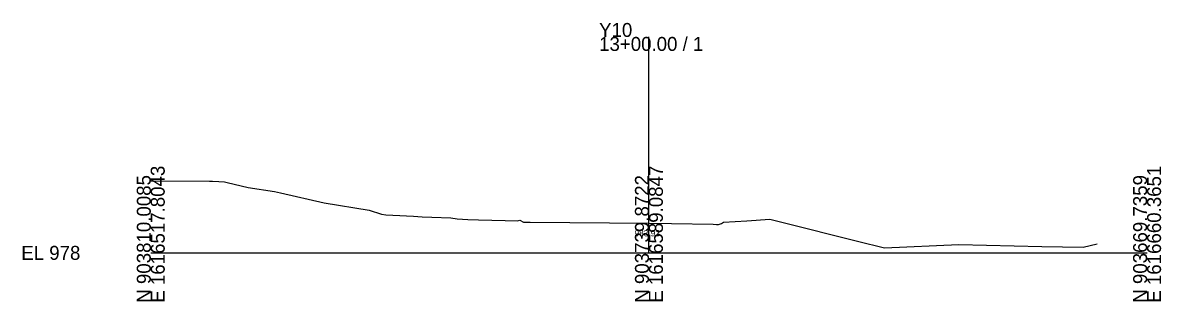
# Model space of a CAD drawing. Extents: x -26 to 203, y -10 to 3046.
# Drawn here: x -25.7 to 202.8, y 2990.3 to 3046.1 of the extents above; entities that cross this region are included whole.
import ezdxf

# ---------------------------------------------------------------- set-up
doc = ezdxf.new("R2010")
doc.units = 0
for name, color, linetype in [('Exist Cross Section Cell', 7, 'Continuous'), ('Exist XS Center Line Elevation Label', 7, 'Continuous'), ('Exist XS Ground Line', 7, 'Continuous')]:
    doc.layers.add(name, color=color, linetype=linetype)

msp = doc.modelspace()

# ---------------------------------------------------------------- linework, layer by layer
at = {"layer": 'Exist Cross Section Cell'}
for p, q in [((100, 3000), (100, 3043.3)), ((0, 3000), (100, 3000)), ((100, 3000), (200, 3000))]:
    msp.add_line(p, q, dxfattribs=at)
at = {"layer": 'Exist XS Ground Line'}
for p, q in [((0, 3014.43), (11.76, 3014.41)), ((11.76, 3014.41), (12.39, 3014.4)), ((12.39, 3014.4), (13.68, 3014.31)), ((13.68, 3014.31), (14.81, 3014.22)), ((14.81, 3014.22), (15.33, 3014.1)), ((15.33, 3014.1), (19.57, 3013.11)), ((19.57, 3013.11), (24.81, 3012.29)), ((24.81, 3012.29), (26.06, 3012.05)), ((26.06, 3012.05), (34.79, 3010.03)), ((34.79, 3010.03), (43.86, 3008.59)), ((43.86, 3008.59), (46.32, 3007.74)), ((46.32, 3007.74), (47.2, 3007.64)), ((47.2, 3007.64), (48.59, 3007.56)), ((48.59, 3007.56), (52.77, 3007.35)), ((52.77, 3007.35), (54.49, 3007.25)), ((54.49, 3007.25), (56.43, 3007.19)), ((56.43, 3007.19), (60.23, 3007.01)), ((60.23, 3007.01), (61.49, 3006.84)), ((61.49, 3006.84), (63.67, 3006.67)), ((63.67, 3006.67), (65.8, 3006.61)), ((65.8, 3006.61), (71.14, 3006.47)), ((71.14, 3006.47), (73.61, 3006.41)), ((73.61, 3006.41), (74.11, 3006.58)), ((74.11, 3006.58), (74.8, 3006.17)), ((74.8, 3006.17), (75.79, 3006.17)), ((75.79, 3006.17), (76.13, 3006.18)), ((76.13, 3006.18), (92.09, 3006.03)), ((92.09, 3006.03), (99.88, 3005.93)), ((99.88, 3005.93), (104.5, 3005.86)), ((104.5, 3005.86), (112.9, 3005.74)), ((112.9, 3005.74), (113.59, 3005.71)), ((113.59, 3005.71), (113.98, 3005.68)), ((113.98, 3005.68), (114.54, 3005.89)), ((114.54, 3005.89), (114.99, 3006.15)), ((114.99, 3006.15), (119.65, 3006.45)), ((119.65, 3006.45), (124.25, 3006.76)), ((124.25, 3006.76), (144.26, 3001.76)), ((144.26, 3001.76), (144.86, 3001.62)), ((144.86, 3001.62), (147.32, 3000.99)), ((147.32, 3000.99), (162.19, 3001.67)), ((162.19, 3001.67), (178.9, 3001.27)), ((178.9, 3001.27), (187.18, 3001.16)), ((187.18, 3001.16), (190.01, 3001.79))]:
    msp.add_line(p, q, dxfattribs=at)

# ---------------------------------------------------------------- texts
at = {"layer": 'Exist Cross Section Cell'}
for s, p in [('Y10', (90, 3043.3)), ('13+00.00 / 1', (90, 3040.5)), ('EL 978', (-26, 2998.6))]:
    msp.add_text(s, height=2.8, dxfattribs=at).set_placement(p)
for s, p in [('E 1616517.8043', (2.8, 2990)), ('E 1616589.0847', (102.8, 2990)), ('E 1616660.3651', (202.8, 2990)), ('N 903810.0085', (0, 2990)), ('N 903739.8722', (100, 2990)), ('N 903669.7359', (200, 2990))]:
    msp.add_text(s, height=2.8, rotation=90, dxfattribs=at).set_placement(p)
at = {"layer": 'Exist XS Center Line Elevation Label'}
msp.add_text('983.93', height=1.25, dxfattribs=at).set_placement((97.1, 3003.31))

doc.saveas('drawing.dxf')
